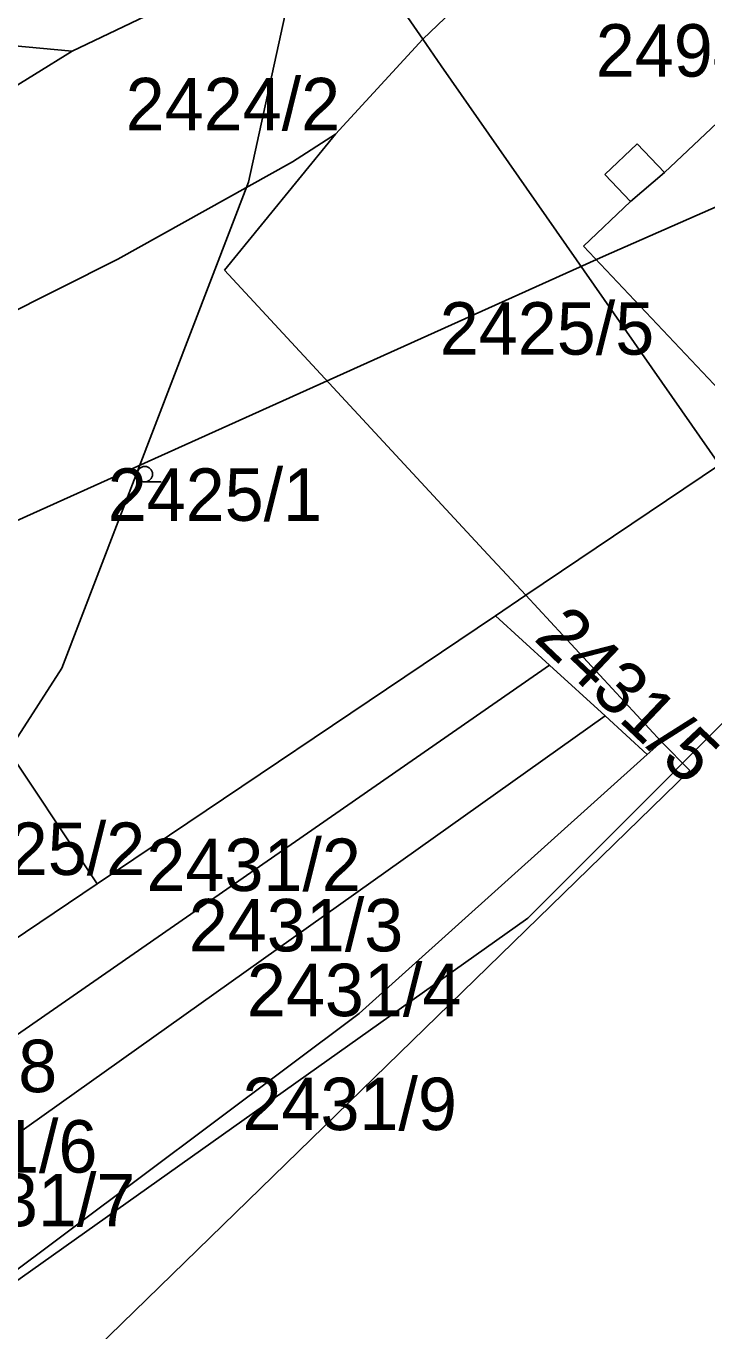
# Model space of a CAD drawing. Extents: x -564810 to -550519, y -1045831 to -1034011.
# Drawn here: x -552740.6 to -552674.4, y -1036713.1 to -1036586.2 of the extents above; entities that cross this region are included whole.
import ezdxf

# ---------------------------------------------------------------- set-up
doc = ezdxf.new("R2010")
doc.units = 0
for name, color, linetype in [('KN stav', 7, 'Continuous'), ('Parcelní čísla', 7, 'Continuous'), ('STG', 7, 'Continuous'), ('Vrstva 33', 7, 'Continuous'), ('Vrstva 4', 7, 'Continuous'), ('zamokř ploch', 7, 'Continuous')]:
    doc.layers.add(name, color=color, linetype=linetype)

msp = doc.modelspace()

# ---------------------------------------------------------------- linework, layer by layer
at = {"layer": 'KN stav'}
for p, q in [((-552714.72, -1036569.05), (-552702.07, -1036587.48)), ((-552685.75, -1036571.91), (-552702.07, -1036587.48)), ((-552736.18, -1036588.65), (-552726.19, -1036583.89)), ((-552744.27, -1036587.88), (-552736.18, -1036588.65)), ((-552702.07, -1036587.48), (-552710.55, -1036596.7)), ((-552700.26, -1036590.08), (-552702.07, -1036587.48)), ((-552736.18, -1036588.65), (-552753.63, -1036599.47)), ((-552673.21, -1036628.87), (-552700.26, -1036590.08)), ((-552672.88, -1036595.1), (-552678.55, -1036600.45)), ((-552710.55, -1036596.7), (-552721.36, -1036609.93)), ((-552714.72, -1036599.39), (-552710.55, -1036596.7)), ((-552681.2, -1036597.65), (-552684.35, -1036600.63)), ((-552678.55, -1036600.45), (-552681.2, -1036597.65)), ((-552731.71, -1036608.87), (-552714.72, -1036599.39)), ((-552684.35, -1036600.63), (-552681.86, -1036603.27)), ((-552681.86, -1036603.27), (-552686.44, -1036607.59)), ((-552686.44, -1036607.59), (-552641.85, -1036654.81)), ((-552743.25, -1036614.62), (-552731.71, -1036608.87)), ((-552721.36, -1036609.93), (-552695.72, -1036637.58)), ((-552692.05, -1036641.54), (-552673.21, -1036628.87)), ((-552695.72, -1036637.58), (-552692.05, -1036641.54)), ((-552692.05, -1036641.54), (-552695, -1036643.53)), ((-552678.85, -1036655.78), (-552692.05, -1036641.54)), ((-552695, -1036643.53), (-552733.74, -1036669.6)), ((-552695, -1036643.53), (-552689.74, -1036648.33)), ((-552689.74, -1036648.33), (-552749.34, -1036689.68)), ((-552733.74, -1036669.6), (-552747.69, -1036648.67)), ((-552689.74, -1036648.33), (-552684.32, -1036653.28)), ((-552744.94, -1036696.34), (-552684.32, -1036653.28)), ((-552684.32, -1036653.28), (-552680.23, -1036657.02)), ((-552678.85, -1036655.78), (-552680.23, -1036657.02)), ((-552676.08, -1036658.57), (-552678.85, -1036655.78)), ((-552680.23, -1036657.02), (-552708.26, -1036682.2)), ((-552739.3, -1036720.09), (-552676.08, -1036658.57)), ((-552733.74, -1036669.6), (-552753.72, -1036683.04)), ((-552708.26, -1036682.2), (-552747.09, -1036711.28))]:
    msp.add_line(p, q, dxfattribs=at)
at = {"layer": 'STG'}
for points in [[(-552406.18, -1036240.18), (-552442.92, -1036277.85), (-552463.13, -1036323.79), (-552479.67, -1036372.48), (-552509.06, -1036422.1), (-552551.31, -1036504.79), (-552576.11, -1036536.95), (-552634.9, -1036615.96), (-552691.85, -1036672.93), (-552770.85, -1036728.98), (-552832.39, -1036818.1), (-552837.9, -1036875.06), (-552831.47, -1036931.11)], [(-553086.83, -1037509.03), (-553102.44, -1037299.55), (-553086.83, -1037209.51), (-553071.21, -1037131.41), (-553050.08, -1037031.26), (-553047.33, -1036952.24), (-553054.68, -1036883.33), (-553078.56, -1036837.39), (-553119.89, -1036809.83), (-553157.55, -1036794.21), (-553196.13, -1036789.62), (-553152.96, -1036760.21), (-553125.41, -1036746.43), (-553070.29, -1036720.71), (-552977.52, -1036697.74), (-552896.69, -1036677.52), (-552848, -1036668.34), (-552776.36, -1036649.96), (-552684.5, -1036608.61), (-552638.57, -1036588.4), (-552609.18, -1036560.84), (-552571.52, -1036514.9), (-552546.72, -1036489.17)]]:
    msp.add_lwpolyline(points, dxfattribs=at)
at = {"layer": 'Vrstva 33'}
msp.add_lwpolyline([(-552896.64, -1036832.02), (-552870.12, -1036811.16), (-552837.42, -1036779.18), (-552809.09, -1036744.29), (-552783.66, -1036724.66), (-552767.68, -1036700.67), (-552758.23, -1036681.34), (-552737.16, -1036648.63), (-552719, -1036601.38), (-552705.2, -1036538.15), (-552687.76, -1036536.69), (-552655.06, -1036539.6), (-552633.27, -1036541.05), (-552585.32, -1036444.38), (-552563.52, -1036392.48), (-552511.94, -1036348.14), (-552488.69, -1036314.71), (-552549.72, -1036441.91)], dxfattribs=at)
at = {"layer": 'Vrstva 4'}
msp.add_line((-552681.86, -1036603.27), (-552678.55, -1036600.45), dxfattribs=at)
at = {"layer": 'zamokř ploch'}
msp.add_line((-552729.1, -1036630.52), (-552727.5, -1036630.52), dxfattribs=at)
msp.add_circle((-552729.1, -1036629.77), 0.75, dxfattribs=at)

# ---------------------------------------------------------------- texts
at = {"layer": 'Parcelní čísla'}
for s, p in [('2494/1', (-552685.23, -1036591.12)), ('2424/2', (-552730.96, -1036596.34)), ('2425/5', (-552700.41, -1036618.15)), ('2425/1', (-552732.71, -1036634.31)), ('2425/2', (-552749.92, -1036668.74)), ('2431/2', (-552728.94, -1036670.3)), ('2431/3', (-552724.82, -1036676.17)), ('2431/4', (-552719.17, -1036682.47)), ('2431/8', (-552758.48, -1036689.86)), ('2431/9', (-552719.6, -1036693.55)), ('2431/6', (-552754.57, -1036697.68)), ('2431/7', (-552750.88, -1036702.9))]:
    msp.add_text(s, height=5.1, dxfattribs=at).set_placement(p)
for s, rotation, p in [('2431/5', 316.4219, (-552691.38, -1036645.83)), ('3087/4', 314.2996, (-552751.04, -1036712.27))]:
    msp.add_text(s, height=5.1, rotation=rotation, dxfattribs=at).set_placement(p)

doc.saveas('drawing.dxf')
